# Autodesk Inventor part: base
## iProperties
Author: Elise Moss
Length Units: 11272
Angle Units: 11279
Time Units: 11290
Mass Units: 11286
Shininess: 3
Angle Display Precision: 2
Document Length Units: 11272
Document Angle Units: 11286
Document Time Units: 11279
Document Mass Units: 11290
Document Length Units Precision: 3
Document Angle Units Precision: 0
Compacted: False
PropertySet Name: _Private Model Information
Created: 2001-09
Part Number: base
Document SubType Name: Modeling
Designer: Elise Moss
Control State: 0
Master: False
Checked Out: False
PropertySet Name: Design Tracking Control
Density: 0.0
Volumn: 0.0
Area: 0.0
PropertySet Name: Model Information
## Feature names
1. Extrusion1
2. Extrusion2
3. Extrusion3
4. Extrusion4
5. Hole1
6. Fillet1
7. Hole2
